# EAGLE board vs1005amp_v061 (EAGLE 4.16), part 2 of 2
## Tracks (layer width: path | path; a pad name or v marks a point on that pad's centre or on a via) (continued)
N$35  (via drill 0.6)
  Top 0.254: U3.8 149.78,19.32 149.23,18.78 149.23,16.87 | 149.23,16.87 R16.2 | 149.31,15.05 R17.1 149.31,16.79 149.23,16.87
  Top 0.305: R17.1 149.31,16.95 150.26,16.95 v150.58,16.63 | v161.38,16 161.38,15.68 161.85,15.2 T1.3 164.87,15.2
  Bottom 0.305: v150.58,16.63 160.74,16.63 v161.38,16
N$36
  Top 0.254: R97.2 68.77,23.09 68.67,22.98 U8.2 67.39,22.97 67.14,22.72 | 67.14,22.72 67.08,22.66 | 67.14,22.72 R99.1 | IC1.12 64.7,24.41 65.17,23.94 66.92,23.94 67.24,23.62 67.24,22.98 67.14,22.88 R99.1 | R99.1 67.14,22.77 67.24,22.66 67.16,22.59 C80.1
N$37
  Top 0.305: U3.30 146.53,29.41 145.98,29.97 145.03,29.97 143.52,31.48 142.72,31.48 142.7,31.5 C41.2
N$38
  Top 0.305: U3.26 149.13,32.69 148.52,33.3
  Top 0.406: 148.52,33.3 C42.2
N$39
  pour Top (no thermals): 148.6,28.06 148.6,31.48 148.04,32.03 147.41,32.67 147.25,32.83 147.25,42.51 144.55,45.21 138.99,45.21 138.83,45.05 138.83,42.35 138.99,42.19 142.8,42.19 146.14,38.86 146.14,32.83 148.36,30.6 148.36,28.06
N$40
  Top 0.254: IC1.13 66.06,25.78 66.13,25.84 66.19,25.78 IC1.14 67.24,26.32 67.4,26.48 68.98,26.48 R100.1
N$41
  Top 0.305: U3.24 150.43,32.67 151.16,33.4
  Top 0.406: 151.22,33.46 151.16,33.4 C43.2
N$42
  Top 0.406: 152.81,33.14 152.86,33.2 C43.1
  pour Top (no thermals): 150.98,28.06 150.98,31.48 151.53,32.03 152.17,32.67 152.33,32.83 152.33,41.32 151.69,41.95 151.69,42.51 151.69,45.21 155.82,45.21 155.98,45.05 155.98,41.4 155.82,41.24 153.44,38.86 153.44,32.83 151.22,30.6 151.22,28.06
N$43
  pour Top (no thermals): 152.49,27.98 152.25,27.98 152.25,30.05 155.9,33.7 156.38,33.7 156.54,33.86 156.54,34.97 156.93,35.37 156.93,37.67 159.39,40.13 163.28,40.13 164.87,41.72 164.87,45.21 169.95,45.21 169.95,42.03 164.87,36.95 160.43,36.95 157.88,34.41 157.88,33.3 157.25,32.67 156.46,32.67 154.55,30.76 153.68,30.76 152.49,29.57
N$44
  Top 0.305: U3.20 153.03,29.4 153.76,30.13 154.87,30.13 156.22,31.48 156.85,31.48 156.88,31.5 C44.2
N$45
  Top 0.254: U3.7 148.7,20.47 148.68,20.44 148.65,20.47 U3.6 148.97,20.47 149.15,20.28 149.15,19.65 148.68,19.17 148.68,18.22 147.88,17.43 | R16.1 147.72,16.95 | R16.1 147.51,17.05 147.88,17.43 | 147.88,17.43 | C40.1 147.41,15.36 147.51,15.46 R16.1
N$46
  Top 0.254: IC21.9 39.46,29.97 40.73,28.7 41.36,28.7 | 43.9,28.7 IC21.5 41.36,28.7 | IC21.2 43.8,26.06 43.9,26.16 IC21.3 42,26.16 41.36,26.79 41.36,28.7
N$47  (via drill 0.6)
  Top 0.254: R15.1 95.34,24.89 95.44,24.99 C23.1 95.44,23.52 96.61,22.35 104.86,22.35 112.16,15.05 v112.16,2.98 | 159.79,8.7 158.52,8.7 157.25,7.43 v157.25,4.57 | C20.- 167.42,10.93 167.41,10.92 167.41,9.65 166.46,8.7 161.06,8.7 159.79,8.7 | 159.79,8.7 R69.1
  Bottom 0.254: v157.25,4.57 154.71,2.03 113.12,2.03 v112.16,2.98
N$49
  Top 0.813: R39.1 144.23,36.32 144.29,36.26 C47.2
N$50
  Top 0.813: C48.2 148.36,34.73 148.52,34.89 R40.1
N$51
  Top 0.813: 151.22,34.73 | 151.22,34.73 C49.2 | R41.1 151.06,34.89 151.22,34.73
N$52
  Top 0.813: R42.1 155.35,36.32 155.29,36.26 C50.2
N$53
  pour Top (no thermals): 147.09,27.98 147.33,27.98 147.33,30.05 143.68,33.7 143.2,33.7 143.04,33.86 143.04,34.97 142.64,35.37 142.64,37.67 140.18,40.13 136.3,40.13 131.22,45.21 125.18,45.21 125.18,42.03 129.63,42.03 134.71,36.95 139.15,36.95 141.69,34.41 141.69,33.3 142.33,32.67 143.04,32.67 143.99,31.79 145.19,30.6 146.06,30.6 147.09,29.57
N$54
  Top 0.254: 45.49,27.43 IC21.4 | 45.49,27.43 46.44,26.48 46.44,21.39 51.52,16.32 C65.2 | IC21.8 39.77,31.24 41.05,29.97 IC21.6 | IC21.6 43.9,29.97 | IC21.6 45.17,29.97 45.81,29.33 45.81,27.74 45.49,27.43
N$55
  Top 0.254: R242.2 64.09,16.45 64.22,16.32 C65.1
N$56
  Top 0.254: C67.2 35.55,19.91 35.65,19.81 R57.1 35.55,17.37 38.5,14.41 56.28,14.41 59.14,11.55 59.09,11.5 CON1.WL
N$57
  Top 0.406: 134.39,59.5 C55.1 R43.2
N$58
  Top 0.406: C56.1 R44.2
N$59
  Top 0.254: C67.1 33.74,21.39 33.84,21.5 R48.2
N$60
  Top 0.203: 78.35,39.89 JP9.1 78.35,41.82 C14.2
N$61
  Top 0.406: 148.68,59.5 C57.1 R45.2
N$62
  Top 0.406: 160.11,59.5 C58.1 R46.2
N$63
  Top 0.254: IC21.13 35.81,24.89 35.65,24.73 R53.2 35.55,23.4 35.65,23.3 35.55,23.2 R48.1
N$64
  Top 0.254: IC21.12 35.81,26.16 35.65,26.32 R55.1 34.12,26.26 34.06,26.32 R54.1 34.06,24.73 33.9,24.57 33.84,24.63 R53.1
N$65
  Top 0.254: R55.2 36.23,27.96 36.76,27.43 IC21.11 37.71,27.43
N$66
  Top 0.254: R56.1 35.81,29.65 36.76,28.7 IC21.10
N$67
  pour Top (no thermals): 109.94,65.21 109.94,63.94 108.99,63.94 108.67,63.62 108.67,62.51 106.61,62.51 106.61,64.89 106.93,65.21
N$68
  pour Top (no thermals): 111.85,71.88 111.85,66.16 114.07,66.16 114.07,65.21 110.58,65.21 110.58,63.94 111.53,63.94 111.85,63.62 111.85,62.51 117.09,62.51 117.56,62.99 117.56,71.56 117.25,71.88
N$69
  Top 0.203: R79.2 25.33,22.82 25.65,22.51 25.65,20.28 25.01,19.65 25.01,15.05 25.65,14.41 25.65,13.77 26.76,12.66 26.76,10.76 LED7.A
N$70
  Top 0.203: R80.2 25.17,24.57 26.12,23.62 | 26.98,14.51 27.08,14.41 | 26.98,14.51 LED6.A | 26.98,14.51 25.8,15.68 25.8,19.33 26.28,19.81 26.28,23.46 26.12,23.62 | 26.12,23.62
N$72
  Top 0.203: R81.2 25.33,26.32 27.08,24.57 27.08,18.54 26.98,18.44 LED5.A 26.92,18.38 26.76,18.54
N$73
  Top 0.203: LED4.A 17.01,18.44 16.91,18.54 16.91,24.57 18.66,26.32 R82.2
N$74
  Top 0.254: C66.+ 81.36,20.45 79.46,22.35 73.11,22.35 72.8,22.66 72.8,22.98 72.9,23.09 R51.1
N$75
  Top 0.203: R83.2 18.82,24.57 17.55,23.3 17.55,20.12 18.34,19.33 18.34,15.84 17.07,14.57 LED3.A
N$76
  Top 0.203: LED2.A 17.01,12.6 19.14,14.73 19.14,19.49 18.19,20.44 18.19,22.35 18.66,22.82 R84.2
N$77  (via drill 0.6)
  Top 0.203: LED1.A 17.01,8.79 v17.23,9.01 | v20.09,19.17 20.09,19.65 19.45,20.28 19.45,20.76 19.56,20.86 R85.2
  Bottom 0.203: v17.23,9.01 17.23,16.32 v20.09,19.17
N$78
  Top 0.203: IC2.11 18.19,32.19 11.52,25.52 11.52,16.32 9.61,14.41 9.61,11.55 13.74,7.43 14.69,7.43 14.91,7.2 | 14.91,7.2 15.01,7.11 | 14.91,7.2 LED1.C
N$79
  Top 0.203: IC2.12 19.45,30.6 18.82,29.97 17.55,29.97 12.79,25.2 12.79,15.05 13.74,14.09 13.74,13.46 14.69,12.5 14.69,10.92 14.85,10.76 LED2.C
N$80
  Top 0.254: R52.1 87.08,23.3 C11.+
N$81
  Top 0.203: IC2.13 20.73,29.65 20.09,29.02 18.19,29.02 13.74,24.57 13.74,15.68 14.91,14.51 | 14.91,14.51 15.01,14.41 | 14.91,14.51 LED3.C
N$82
  Top 0.203: LED4.C 14.91,24.16 18.5,27.74 21.04,27.74 21.99,28.7 IC2.14
N$83
  Top 0.203: IC2.15 23.27,28.7 24.22,27.74 25.49,27.74 28.98,24.25 28.98,18.54 29.08,18.44 LED5.C
N$84
  Top 0.203: IC2.16 24.53,29.65 25.17,29.02 25.8,29.02 30.25,24.57 30.25,15.68 29.14,14.57 LED6.C
N$85
  Top 0.203: IC2.17 25.8,30.92 31.2,25.52 31.2,14.73 29.3,12.82 29.3,10.92 29.08,10.7 | 29.08,10.7 28.98,10.6 | 29.08,10.7 LED7.C
N$86
  Top 0.203: IC2.18 27.08,31.55 32.16,26.48 32.16,16.32 34.38,14.09 34.38,11.55 30.25,7.43 29.3,7.43 29.14,7.27 LED8.C
N$87
  Top 0.203: JP6.1 118.83,76.96 118.2,76.32 R87.2
N$88
  Top 0.203: C15.2 75.81,42.45 JP9.2
N$89  (via drill 0.6)
  Top 0.254: 93.43,25.2 C22.1 | R14.1 93.27,25.36 93.43,25.2 | 93.43,25.2 93.43,23.3 95.97,20.76 103.59,20.76 108.35,16 108.35,4.57 v109.94,2.98 | C36.- 167.41,3.3 166.99,3.72 R88.1 159.79,3.62 157.88,3.62 v157.25,2.98
  Bottom 0.254: v157.25,2.98 155.66,1.39 111.53,1.39 v109.94,2.98
N$90
  Top 0.254: U3.14 153.68,18.93 154.07,18.54 155.98,18.54 156.62,17.9 R93.2 156.04,16.85 155.66,16.47 155.66,13.46 156.62,12.5 R89.1
N$103
  Top 0.203: C15.1 75.97,44.26 | C15.1 | L2.2 75.97,45.95 C15.1
N$119
  Top 0.254: U3.15 154.33,19.55 154.71,19.17 157.57,19.17 158.52,18.22 158.52,16.95 | 158.52,16.63 R94.2 158.52,16.95 | 158.52,16.95 157.88,16.95 157.57,16.63 157.57,13.46 158.52,12.5 R91.1
N$120
  Top 0.254: U3.13 153.03,19.58 153.12,19.49 153.12,18.54 153.76,17.9 154.39,17.9 154.71,17.59 R92.2 153.97,16.85 153.6,16.47 153.6,13.46 154.71,12.35 R90.1
N$121  (via drill 0.6)
  Top 0.254: U3.11 151.73,18.66 v151.85,18.54 | 164.24,19.17 C39.+ v160.11,19.17 R5.1
  Bottom 0.254: v151.85,18.54 159.47,18.54 v160.11,19.17
N$122  (via drill 0.6)
  Top 0.254: 163.6,12.5 163.6,11.23 C20.+ 164.24,11.23 | R18.1 160.32,12.4 160.43,12.5 163.6,12.5 | U3.10 151.08,19.35 150.9,19.17 150.9,17.9 v151.22,17.59 | v162.65,13.77 163.28,13.77 163.6,13.46 163.6,12.5
  Bottom 0.254: v151.22,17.59 161.38,17.59 162.33,16.63 162.33,14.09 v162.65,13.77
N$232
  Top 0.254: 66.63,13.64 66.76,13.77 R243.1 66.76,10.6 67.08,10.28 67.05,10.25 CON1.RL
  Top 0.305: 66.92,13.62 R243.1 | 66.92,13.62 R242.1 | 67.08,13.46 66.92,13.62
N$245
  Top 0.406: IC21.14 37.87,23.62 C221.2 39.67,21.93 39.77,22.03 L16.2
OUTN_LEFT
  pour Top (no thermals): 168.76,52.83 164.87,52.83 164.87,59.81 163.6,61.08 161.46,61.08 161.46,62.35 161.06,62.75 159.31,62.75 152.96,69.1 152.96,71.32 153.68,72.04 156.54,72.04 168.76,59.81
OUTN_RIGHT
  pour Top (no thermals): 142.96,70.61 142.96,70.92 143.92,71.88 144.87,71.88 146.14,70.61 146.14,65.21 146.45,64.89 146.45,62.83 144.95,62.83 144.39,62.27 144.39,61.16 142.41,61.16 142.01,60.77 142.01,56.88 142.64,56.24 142.64,52.91 142.49,52.75 138.99,52.75 138.76,52.99 138.76,63.38 142.96,67.59 142.96,70.69
OUTP_LEFT
  pour Top (no thermals): 150.9,71.24 150.26,71.88 149,71.88 148.04,70.92 148.04,62.83 149.55,62.83 150.11,62.27 150.11,61.16 152.09,61.16 152.49,60.77 152.49,56.88 151.85,56.24 151.85,52.91 152.01,52.75 155.5,52.75 155.74,52.99 155.74,62.11 150.9,66.96
OUTP_RIGHT
  pour Top (no thermals): 125.42,52.51 129.63,52.51 129.63,59.81 130.9,61.08 133.04,61.08 133.04,62.35 133.68,62.99 135.42,62.99 140.74,68.31 140.74,70.85 140.74,71.48 140.58,71.64 140.34,71.88 140.34,71.88 140.18,72.04 137.96,72.04 125.42,59.5
PBTN  (via drill 0.6)
  Top 0.203: U1.63 74.09,55.66 v73.67,56.08 | JP10.1 24.85,77.28 41.68,60.45 54.38,60.45 55.02,59.81 55.65,59.81 55.73,59.89 R3.2 | R3.2 55.71,59.87 | R3.2 R4.1 | R4.1 57.18,59.87 57.24,59.81 | R4.1 57.08,59.97 56.92,60.13 59.86,60.13 v60.02,59.97 | v60.02,59.97
  Bottom 0.203: v73.67,56.08 73.67,57.19 71.05,59.81 60.09,59.81 60.02,59.89 v60.02,59.97
PD_3V3  (via drill 0.6)
  Top 0.203: U1.16 87.37,60.46 91.48,64.58 94.07,64.58 v94.38,64.89 94.7,65.21 R72.2 | v40.09,60.45 40.09,55.69 32.47,48.06 v32.47,40.13 | v35.01,40.13 35.33,39.81 36.28,39.81 U7.3
  Bottom 0.203: v94.38,64.89 94.38,65.21 91.21,68.38 73.11,68.38 72.8,68.7 53.43,68.7 50.57,65.84 45.49,65.84 v40.09,60.45 | v32.47,40.13 v35.01,40.13
PWM
  Top 0.203: PWM.TP 85.18,52.83 84.53,53.48 U1.88
R1  (via drill 0.6)
  Top 0.254: 77.24,30.6 77.14,30.5 C38.1 77.24,29.02 | U$39.8 77.24,23.3 | U$39.8 R51.2 | U$39.8 78.83,23.3 79.46,23.94 79.46,28.38 78.83,29.02 77.24,29.02 | 77.24,29.02 | U5.3 79.85,36.57 v79.46,36.95 | v79.46,30.29 79.14,30.6 77.24,30.6 | 77.24,30.6 R50.1
  Bottom 0.254: v79.46,30.29 v79.46,36.95
R2  (via drill 0.6)
  Top 0.254: 60.89,30.76 | 60.89,30.76 IC1.6 60.89,32.98 61.05,33.14 R31.2 61.1,34.67 61.05,34.73 C28.1 | 62.95,22.03 R19.1 62.79,22.82 62.48,23.14 v62.48,23.62 | 60.89,30.76 60.89,28.86 v61.05,28.7 60.97,28.7 60.9,28.63 U2.3
  Bottom 0.254: v62.48,23.62 62.48,27.27 v61.05,28.7
R11
  Top 0.254: 79.85,32.58 U5.10 79.85,31.94 79.46,31.55 78.51,31.55 78.19,31.87 R60.2
R12
  Top 0.254: R59.2 77.24,33.14 77.56,32.83 78.19,32.83 78.51,32.51 79.14,32.51 79.23,32.59 U5.9
R21  (via drill 0.6)
  Top 0.254: U2.10 50.8,28.63 v50.57,28.86 | 56.28,30.6 R22.2 v55.02,30.6
  Bottom 0.254: v50.57,28.86 53.27,28.86 v55.02,30.6
R22  (via drill 0.6)
  Top 0.254: R30.2 v54.38,31.87 | 51.68,29.17 51.73,29.13 U2.9 51.77,29.4 51.2,29.97 v50.57,29.97
  Bottom 0.254: v50.57,29.97 52.63,29.97 52.95,29.97 54.22,31.24 | v54.38,31.87 54.38,31.4 54.22,31.24 | 54.22,31.24
R2222
  Top 0.254: U$39.5 76.29,27.11 75.34,28.06 75.34,28.7 75.44,28.8 C38.2 75.44,30.5 75.34,30.6 | R59.1 75.44,31.98 75.34,31.87 R60.1 75.44,30.7 75.34,30.6 | 75.34,30.6 R50.2 75.65,30.6 75.34,30.92 73.43,30.92 R23.1
RCAP  (via drill 0.6)
  Top 0.254: 78.82,46.84 79.77,47.79 79.77,49.54 80.53,50.29 U1.78 | 78.82,46.84 CR1.1 | 78.82,46.84 78.82,44.26 v78.99,44.1 | v65.49,34.09 65.49,33.06 64.78,32.35 64.78,31.16 64.7,31.08 IC1.3 64.7,29.65 65.97,28.38 68.98,28.38 R100.2
  Bottom 0.254: v78.99,44.1 78.99,43.46 77.88,42.35 72.8,42.35 65.49,35.05 v65.49,34.09
RFN
  Top 0.203: U1.75 79.33,51.32 77.07,49.06 76.87,48.86 76.53,48.86 76.29,48.62 76.29,47.99 | 76.29,47.99 76.29,47.75 76.19,47.75 L2.1 76.29,47.96 76.29,47.99 | 76.29,47.99 76.29,48.27
RFP
  Top 0.203: U1.76 79.73,51.08 77.55,48.9 77.48,48.83 L1.1 77.45,47.75 77.56,47.75
RIGHT
  Top 0.254: U1.80 81.33,53.06 81.68,52.71 81.68,46.36 81.69,46.35 81.69,44.89 80.41,43.62 R12.2 80.41,43.14 81.21,43.14 81.37,42.98 81.37,37.67 82.56,36.48 86.29,36.48 93.27,29.49 R14.2
RTCVDD  (via drill 0.6)
  Top 0.254: 68.82,54.78 68.85,54.75 CRTC1.1 | U1.64 73.64,55.26 73.43,55.05 70.25,55.05 D1.C
  Top 0.406: CRTC1.1 68.85,54.65 68.85,54.76 68.91,54.81 70.18,54.81 D1.C | 68.85,54.75 68.6,54.75 68.59,54.73 68.59,53.62 v68.67,53.54 | v68.67,53.54 | D1.C 70.33,54.97 | D1.C
RX
  Top 0.203: U1.37 78.93,65.78 77.87,66.84 77.87,72.08 76.44,73.51 76.44,74.25 76.61,74.42 R74.2 76.39,74.63 76.29,74.73 76.29,76 75.97,76.32 JP2.2
SCK  (via drill 0.6)
  Top 0.203: U1.45 75.02,62.86 72.95,64.94 72.95,67.63 72.63,67.95 68.5,72.08 55.13,72.08 v51.84,75.37 | CN1.5 5.45,9.68 1.36,13.77 v1.36,19.49
  Bottom 0.203: v51.84,75.37 31.52,75.37 1.36,45.21 v1.36,19.49
SCLK0
  Top 0.203: U1.28 82.53,68.96 85.65,72.08 87.23,72.08 92.05,72.08 94.38,74.42 U4.6 100.1,74.42 100.73,75.05 104.55,75.05 105.18,75.69 JP8.3
SD0  (via drill 0.6)
  Top 0.203: U1.46 74.78,62.46 72.31,64.94 72.31,67.32 68.7,70.92 54.7,70.92 v51.2,74.42 | R63.1 3.32,7.84 3.34,7.82 3.42,7.9 | v1.36,8.7 1.99,8.06 3.26,8.06 R63.1 | R63.1 3.26,7.74 3.25,7.73 CN1.7
  Bottom 0.203: v51.2,74.42 32.16,74.42 2.31,44.57 2.31,18.22 1.36,17.27 v1.36,8.7
SD1  (via drill 0.6)
  Top 0.203: U1.47 74.55,62.06 71.68,64.94 71.68,66.84 68.66,69.86 53.86,69.86 v50.25,73.47 | v1.36,7.11 1.83,7.11 2.15,6.79 2.15,5.44 CN1.8
  Bottom 0.203: v50.25,73.47 33.11,73.47 6.76,47.11 6.76,21.08 1.99,16.32 1.99,13.77 2.31,13.46 2.31,8.06 v1.36,7.11
SD2  (via drill 0.6)
  Top 0.203: U1.48 74.31,61.66 71.04,64.94 71.04,66.33 68.67,68.7 52.95,68.7 v48.98,72.67 | CN1.1 9.85,9.73 v7.71,11.87
  Bottom 0.203: v48.98,72.67 33.58,72.67 7.71,46.8 7.71,16.63 8.02,16.32 8.02,14.09 7.71,13.77 v7.71,11.87
SD3  (via drill 0.6)
  Top 0.203: U1.49 74.08,61.26 70.41,64.94 70.41,66.05 69.14,67.32 52.27,67.32 v48.03,71.56 | CN1.2 8.75,6.56 v8.98,6.79
  Bottom 0.203: v48.03,71.56 34.06,71.56 8.66,46.16 8.66,12.82 8.98,12.5 8.98,9.33 8.02,8.38 8.02,7.74 v8.98,6.79
SPIN
  Top 0.203: U1.56 72.43,58.46 71.04,59.86
  Top 0.254: R56.2 33.84,47.53 43.27,56.95 57.55,56.95 59.78,59.18 63.27,59.18 63.95,59.86 71.04,59.86
SPOUT  (via drill 0.6)
  Top 0.203: U1.57 72.2,58.06 70.88,59.38 | 70.88,59.38 69.93,59.38 | 70.88,59.38
  Top 0.254: 44.54,23.62 IC21.1 42,23.62 v40.73,24.89 | 70.88,59.38 64.74,59.38 63.91,58.54 60.09,58.54 57.87,56.32 46.12,56.32 40.73,50.92 v40.73,32.83
  Bottom 0.254: v40.73,32.83 v40.73,24.89
STBY  (via drill 0.6)
  Top 0.203: U1.22 85.33,64.78 89.3,68.75 90.57,68.75 92.11,70.29 99.47,70.29 v99.78,70.61 | R37.2 143.7,18.12 v143.6,18.22 | v106.13,49.02 106.13,49.65 105.5,50.29 R101.1
  Bottom 0.203: v143.6,18.22 143.6,18.54 143.92,18.86 143.92,20.12 143.6,20.44 141.06,20.44 135.34,26.16 112.16,26.16 108.04,30.29 108.04,47.11 v106.13,49.02 100.73,54.41 100.73,67.11 99.78,68.07 v99.78,70.61
TRIG_IN
  Top 0.203: U1.23 84.53,64.93 88.98,69.38 90.3,69.38 91.84,70.92 98.83,70.92 101.69,73.78 116.29,73.78 | 116.29,73.78 R86.1 | R87.1 116.51,73.57 116.29,73.78
TX
  Top 0.203: U1.38 78.53,65.54 77.39,66.68 77.39,71.73 73.43,75.69 JP2.3
USBN
  Top 0.254: U1.86 83.73,51.46 85,50.19 85,48.25 87.14,46.11 87.14,42.29 87.56,41.87 87.61,41.87 C24.2 | C24.2 87.88,41.72 | 87.72,41.72 87.56,41.72 | R9.1 88.19,42.83 88.03,42.67 88.03,42.03 87.72,41.72 | 87.72,41.72 C24.2 | 87.72,41.72 87.16,41.21 87.16,41 88.83,39.33 | 88.83,39.33 | 88.83,39.33 90.65,37.51 95.41,37.51 118.83,14.09 118.83,12.35 119.47,11.71 X2.2
USBP
  Top 0.254: U1.85 83.33,51.22 83.58,50.97 84.54,50.01 84.54,48.06 86.68,45.92 86.68,42.27 86.45,42.03 86.45,41.87 | 86.45,41.87 86.23,41.87 C24.1 86.13,41.72 85.81,42.03 85.81,42.67 85.65,42.83 R8.1 | 86.45,41.87 86.45,41.4 86.71,41.14 86.71,40.79 90.44,37.05 95.23,37.05 118.36,13.95 118.36,10.76 119.45,9.66 | 119.45,9.66 119.47,9.65 | 119.45,9.66 X2.3
VCC  (via drill 0.6)
  Top 0.203: v158.52,13.77 R94.1 | R36.2 v152.49,13.77
  Top 0.254: R93.1 v156.62,13.77 | R92.1 v154.71,13.77 | v145.34,12.11 R95.2
  Top 0.813: U$5.3 114.15,45.77 114.07,45.84 114.07,46.8 113.59,47.27 CC5.1 113.65,47.33 113.75,47.43 113.75,51.56 115.34,53.14 117.56,53.14 117.88,53.46 C76.+
  Top 1.778: C76.+ 117.94,53.41 118.2,53.14 118.52,53.46
  Route3 0.203: 158.2,13.77 v158.52,13.77 | v152.49,13.77 152.81,13.77
  Route3 0.254: v156.62,13.77 156.93,13.77 | v154.71,13.77 155.03,13.77 | v145.34,12.11 145.34,12.27
  other vias: 136.3,30.6 138.83,30.6 140.11,30.6 140.11,29.33 138.83,29.33 136.3,29.33 161.06,29.97 162.49,29.97 163.92,29.97 163.92,28.38 162.49,28.38 162.49,31.55 163.92,31.55 137.56,30.6 137.56,29.33 161.06,31.55 161.06,28.38 137.56,28.06 136.3,28.06
  pour Top (no thermals): 144.15,28.7 139.15,28.7 136.61,26.16 131.85,26.16 131.85,28.7 127.41,33.14 126.14,33.14 125.82,32.83 125.82,31.24 123.91,31.24 123.91,36.63 126.45,36.63 127.41,35.68 131.22,35.68 131.53,35.37 131.53,33.46 132.17,32.83 134.07,32.83 135.66,31.24 140.74,31.24 142.01,29.97 144.15,29.97 144.79,29.33 145.82,29.33 145.82,27.98 144.87,27.98
  pour Top (no thermals): 123.91,34.09 123.59,33.78 120.42,33.78 120.1,34.09 120.1,52.83 116.93,54.41 116.93,32.19 117.88,31.24 124.55,31.24 124.55,34.41 123.91,34.41
  pour Top (no thermals): 166.78,35.37 166.78,25.52 162.97,25.52 159.79,28.7 155.98,28.7 155.34,28.06 155.34,28.06 155.19,27.9 153.68,27.9 153.6,27.98 153.6,29.17 153.76,29.33 155.03,29.33 155.66,29.97 159.08,29.97 162.17,33.06 162.17,34.81 162.81,35.44 166.7,35.44
  pour Top (no thermals): 111.85,61.72 111.85,61.08 116.61,61.08 117.88,59.81 117.88,57.27 116.61,56 116.61,53.46 120.1,51.88 120.1,60.45 118.83,61.72
  pour Route3 (no thermals): 135.34,31.24 135.34,27.43 164.55,27.43 164.55,32.51 136.61,32.51
  pour Route3 (no thermals): 135.34,29.65 135.34,23.62 138.52,20.44 143.6,20.44 144.55,19.49 144.55,11.23 145.82,11.23 145.82,12.19 146.45,12.82 158.84,12.82 159.47,13.46 159.47,15.05 158.84,15.68 148.04,15.68 147.09,16.63 147.09,19.81 144.87,22.03 139.79,22.03 137.88,23.94 137.88,29.65
VHIGH  (via drill 0.6)
  Top 0.203: v88.51,51.48 88.51,51.72 88.63,51.6 | 89.62,51.72 | 89.62,51.72 v89.62,51.48 | 89.77,51.6 89.74,51.6 89.62,51.72
  Top 0.254: 88.63,51.6 88.82,51.6 | 86.82,55.51 86.79,55.51 86.63,55.66 U1.4
  Top 0.305: 86.82,55.51 88.03,54.3 88.03,52.08 | CP1.1 52.58,58.96 53.11,59.5 v54.06,59.5
  Top 0.406: 88.03,52.08 88.5,51.6 | R81.1 22.73,26.26 22.63,26.16 22.47,26.32 R82.1 21.26,26.26 21.36,26.16 21.26,26.05 R83.1 R84.1 | R81.1 22.73,24.67 22.63,24.57 | R84.1 21.26,22.77 21.36,22.66 | R85.1 21.36,21.08 21.26,21.18 R84.1 | 22.63,24.57 R80.1 | 22.63,24.57 22.73,24.47 R79.1 22.73,22.77 22.63,22.66 22.73,22.56 R78.1 | R81.1 22.73,21.18 22.63,21.08
  Top 0.61: CH1.1 | 89.77,51.6 CH1.1 | 89.77,51.6 88.63,51.6 88.5,51.6 | 89.77,51.6
  Top 0.813: U7.1 38.19,41.71 38.19,41.72 C78.1 38.11,41.72 | IC2.10 16.14,33.32 v15.01,32.19 | v37.08,43.3 v38.19,43.3 38.19,41.79 38.11,41.72 | 38.11,41.72
  Top 1.016: 22.63,21.08 21.99,21.08 | 21.99,21.08 21.36,21.08 | 21.99,21.08 v21.99,19.49 v21.99,18.22
  Route3 0.305: v54.06,59.5 54.06,56.95
  Route3 0.406: v97.88,71.88 100.73,71.88 101.37,71.24 101.37,53.46 98.19,50.29 91.21,50.29 v91.21,50.37
  Route3 0.813: v15.01,32.19 15.33,32.19
  Bottom 0.406: JP4.1 67.72,75.69 68.67,74.73 80.41,74.73 81.53,75.85 86.45,75.85 88.99,78.39 92.64,78.39 93.04,77.99 93.04,75.61 94.7,73.94 96.45,73.94 97.88,72.51 v97.88,71.88
  other vias: 90.1,50.37 88.99,50.37
  pour Top (no thermals): 107.09,71.88 108.67,71.88 108.67,66.16 106.45,66.16 105.5,65.21 105.5,59.81 106.13,59.18 108.67,59.18 108.67,58.54 103.91,58.54 103.28,57.91 103.28,52.51 101.69,52.51 101.69,59.18 103.59,61.08 103.59,68.38
  pour Top (no thermals): 88.03,52.03 88.03,50.76 88.83,49.97 95.02,49.97 95.97,50.92 100.42,50.92 101.85,52.35 102.96,52.35 103.12,52.51 103.12,54.26 103.28,54.41 101.69,54.41 99.15,51.88 95.34,51.88 94.07,50.61 91.53,50.61 91.21,50.92 91.21,51.88 91.05,52.03
  pour Route3 (no thermals): 90.58,51.88 88.67,51.88 84.54,56 69.3,56 68.03,57.27 38.5,57.27 9.3,28.06 9.3,16.63 30.57,16.63 30.89,16.95 30.89,35.37 50.89,55.37 64.86,55.37 65.81,54.41 84.22,54.41 88.03,50.61 90.58,50.61
VREF  (via drill 0.6)
  Top 0.254: 62.16,28.7 IC1.10 | 70.89,29.65 C35.1 | R10.2 70.79,29.75 70.89,29.65 | 70.89,29.65 70.89,28.54 v70.57,28.22 | 62.16,28.7 IC1.5 | v62.95,28.7 62.16,28.7
  Top 0.406: U$39.2 84.7,24.57 v85.02,24.89 C45.2
  Bottom 0.254: 70.41,28.22 69.94,28.7 v62.95,28.7
  Bottom 0.305: 70.41,28.22 v70.57,28.22 70.57,26.79 73.43,23.94 84.07,23.94 v85.02,24.89
XCD  (via drill 0.6)
  Top 0.203: U1.35 79.73,71.37 v78.83,72.27 | CN1.12 12.71,1.32 13.1,1.71 v13.42,2.03
  Bottom 0.203: 78.67,72.51 78.67,72.43 v78.83,72.27 78.75,72.27 78.51,72.51 52.48,72.51 48.98,69.02 35.97,69.02 14.06,47.43 14.06,17.27 15.33,16 15.33,3.93 v13.42,2.03
XCS0  (via drill 0.6)
  Top 0.203: U1.27 82.93,68.41 84.06,69.54 85.96,71.44 94.27,71.44 v94.7,71.88 | U4.1 89.94,76.96 | v92.16,76.96 U4.1 | U4.1 89.62,76.96 89.41,77.17 R62.2 86.13,78.55 85.81,78.23 JP3.1
  Bottom 0.203: v92.16,76.96 92.16,74.42 v94.7,71.88
XCS1  (via drill 0.6)
  Top 0.203: U1.19 86.5,61.66 91.04,66.21 92.16,66.21 94.97,69.02 v98.67,69.02 | JP8.2 102.64,76 102.32,75.69 98.83,75.69 v98.67,75.53
  Bottom 0.203: v98.67,69.02 v98.67,75.53
XRST  (via drill 0.6)
  Top 0.203: U1.8 89.25,57.26 90.17,58.19 93.79,58.19 v94.54,57.43 94.54,57.11 95.97,55.69 R73.2 | JP10.2 27.39,76 41.52,61.88 v42.95,61.88 | v46.28,61.88 v65.65,61.88
  Bottom 0.203: v94.54,57.43 93.75,58.23 87.4,58.23 83.59,62.03 71.05,62.03 70.41,61.4 66.13,61.4 v65.65,61.88 | v42.95,61.88 v46.28,61.88
XTI
  Top 0.203: U1.2 85.88,54.86 86.76,53.98 86.76,49.22 88.34,47.63 90.25,47.63 90.37,47.63 92.48,45.52 98.51,45.52 100.73,43.3 | XT2.2 100.83,43.39 100.73,43.3 | 100.73,43.3 100.52,43.09 C2.2 100.42,39.81 | 100.42,39.81 R1.1 | 100.42,39.81
XTIR
  Top 0.203: U1.66 74.7,54.46 74.22,53.98 71.73,53.98 69.94,52.19 64.22,52.19 63.91,52.51 63.81,52.41 | C1.2 63.37,51.98 63.59,52.19
  Top 0.406: 63.61,52.21 63.75,52.35 | 63.61,52.21 XT1.2 63.53,52.21 | 63.61,52.21 63.59,52.19 | 63.53,52.21 63.51,52.19 | 63.81,52.41 63.73,52.41 63.53,52.21
XTO
  Top 0.203: U1.1 85.49,54.46 86.28,53.66 86.28,48.9 88.19,47 90.06,47 92.48,44.57 92.48,43.62 92.51,43.59 XT2.1 92.51,43.33 92.48,43.3 94.38,43.3 94.28,43.2 C4.2 96.61,39.81 R1.2
XTOR
  Top 0.203: U1.65 73.99,54.86 73.58,54.46 71.57,54.46 69.78,52.67 65.97,52.67 65.49,53.14 65.49,53.46 65.17,53.78 64.86,54.1 64.54,54.1 63.91,54.73 63.88,54.71 XT1.1 63.59,55.69 62.42,56.85 C3.2

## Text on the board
Top: 1
GND: 2
Route3: 3
Bottom: 4
tPlace: ETH | IR | R+ | R- | L+ | L- | I2S | GND | TX | RX | 3V3 | BOOT | SPI | PBTN | XRST | > | SP OUT | > | VS1005 Amp Board v1.0 | VLSI Solution Oy 2014 | N | P | - | + | CON1
Measures: 1250 | 1175 | 700 | 37.5 | 2750 | 1500 | 69.85 mm | 38.1 mm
